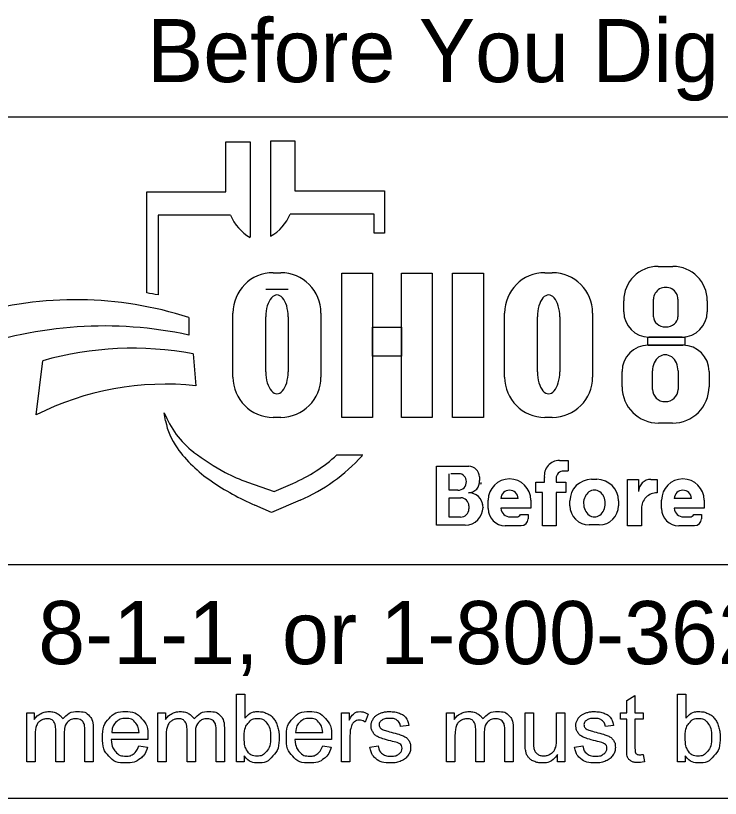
# Model space of a CAD drawing. Extents: x 0 to 34, y 0 to 22.
# Drawn here: x 3.267 to 4.831, y 2.143 to 3.88 of the extents above; entities that cross this region are included whole.
import ezdxf

# ---------------------------------------------------------------- set-up
doc = ezdxf.new("R2010")
doc.units = 0
doc.layers.add('GM_X_Minor_Lake', color=7, linetype='Continuous')
doc.layers.add('GM_X_Minor_Lake_Text', color=7, linetype='Continuous')

msp = doc.modelspace()

# ---------------------------------------------------------------- linework, layer by layer
at = {"layer": 'GM_X_Minor_Lake'}
for p, q in [((3.7335, 3.4883), (3.7335, 3.5998)), ((3.7335, 3.5998), (3.7872, 3.5998)), ((3.7872, 3.5998), (3.7872, 3.3877)), ((3.8329, 3.39), (3.8329, 3.6021)), ((3.8329, 3.6021), (3.8865, 3.6021)), ((3.8865, 3.6021), (3.8865, 3.4906)), ((3.5576, 3.2644), (3.5576, 3.4883)), ((3.5576, 3.4883), (3.7335, 3.4883)), ((3.8865, 3.4906), (4.0857, 3.4906)), ((4.0857, 3.4906), (4.0857, 3.3968)), ((4.0625, 3.4392), (3.8761, 3.4392)), ((4.0625, 3.3968), (4.0625, 3.4392)), ((3.5828, 3.4369), (3.5828, 3.26)), ((3.7439, 3.4369), (3.5828, 3.4369)), ((4.0857, 3.3968), (4.0625, 3.3968)), ((4.6931, 3.3231), (4.7258, 3.3231)), ((3.8385, 3.3091), (3.8551, 3.3091)), ((4.4416, 3.3091), (4.4581, 3.3091)), ((3.8718, 3.2721), (3.822, 3.2721)), ((4.683, 3.2111), (4.683, 3.2504)), ((4.7371, 3.2504), (4.7371, 3.2111)), ((4.6168, 3.2225), (4.6168, 3.2468)), ((4.8022, 3.2468), (4.8022, 3.2225)), ((3.7491, 3.0776), (3.7491, 3.2196)), ((3.9445, 3.2196), (3.9445, 3.0776)), ((4.3521, 3.0776), (4.3521, 3.2196)), ((4.5476, 3.2196), (4.5476, 3.0776)), ((3.6509, 3.2097), (3.6509, 3.1709)), ((3.822, 3.089), (3.822, 3.2114)), ((3.8718, 3.2114), (3.8718, 3.089)), ((4.425, 3.089), (4.425, 3.2114)), ((4.4748, 3.2114), (4.4748, 3.089)), ((4.7462, 3.1665), (4.6728, 3.1665)), ((4.671, 3.1482), (4.7483, 3.1482)), ((3.6608, 3.1291), (3.6671, 3.0582)), ((3.312, 2.9936), (3.3267, 3.1137)), ((4.6131, 3.0563), (4.6131, 3.0903)), ((4.6806, 3.0503), (4.6806, 3.0912)), ((4.7374, 3.0912), (4.7374, 3.0503)), ((4.8062, 3.0903), (4.8062, 3.0563)), ((3.5997, 2.9807), (3.5967, 2.9986)), ((3.8551, 2.9882), (3.8385, 2.9882)), ((4.4581, 2.9882), (4.4416, 2.9882)), ((4.7252, 2.9753), (4.6941, 2.9753)), ((3.98, 2.9048), (4.0375, 2.9048)), ((4.4739, 2.8926), (4.4934, 2.8926)), ((4.4934, 2.8926), (4.4934, 2.8696)), ((4.2013, 2.749), (4.2013, 2.8798)), ((4.2013, 2.8798), (4.2725, 2.8798)), ((4.4934, 2.8691), (4.4832, 2.8691)), ((4.2293, 2.8263), (4.2293, 2.8632)), ((4.2545, 2.8632), (4.2332, 2.8632)), ((4.2963, 2.856), (4.2963, 2.8481)), ((4.4406, 2.8442), (4.4406, 2.8546)), ((4.4667, 2.8526), (4.4667, 2.8442)), ((4.5451, 2.8508), (4.5573, 2.8508)), ((4.6254, 2.7478), (4.6254, 2.8505)), ((4.6254, 2.8505), (4.6499, 2.8505)), ((4.6499, 2.8505), (4.6499, 2.8237)), ((4.6772, 2.8505), (4.691, 2.8505)), ((4.691, 2.8505), (4.691, 2.8209)), ((3.7816, 2.8444), (3.841, 2.8239)), ((3.841, 2.8239), (3.8821, 2.8417)), ((4.4213, 2.8212), (4.4213, 2.8442)), ((4.4213, 2.8442), (4.4406, 2.8442)), ((4.4667, 2.8442), (4.4883, 2.8442)), ((4.4883, 2.8442), (4.4883, 2.8212)), ((4.2487, 2.8263), (4.2293, 2.8263)), ((4.4362, 2.8212), (4.4213, 2.8212)), ((4.4362, 2.7478), (4.4362, 2.8212)), ((4.4883, 2.8212), (4.4667, 2.8212)), ((4.4667, 2.8212), (4.4667, 2.7478)), ((3.8983, 2.8044), (3.835, 2.7769)), ((4.2293, 2.7669), (4.2293, 2.8097)), ((4.2293, 2.8097), (4.2548, 2.8097)), ((4.3159, 2.7858), (4.3159, 2.8042)), ((4.3824, 2.8082), (4.3439, 2.8082)), ((4.4104, 2.8042), (4.4104, 2.7866)), ((4.4973, 2.7922), (4.4973, 2.8029)), ((4.6051, 2.8029), (4.6051, 2.7922)), ((4.7008, 2.7858), (4.7008, 2.8042)), ((4.7674, 2.8082), (4.7288, 2.8082)), ((4.7953, 2.8042), (4.7953, 2.7866)), ((3.835, 2.7769), (3.7976, 2.7934)), ((4.2729, 2.7916), (4.2729, 2.7853)), ((4.3043, 2.7887), (4.3043, 2.7884)), ((4.4104, 2.7866), (4.344, 2.7866)), ((4.6559, 2.786), (4.6559, 2.7478)), ((4.7953, 2.7866), (4.7289, 2.7866)), ((4.2546, 2.7669), (4.2293, 2.7669)), ((4.3649, 2.7673), (4.379, 2.7673)), ((4.3876, 2.7729), (4.4045, 2.7729)), ((4.4045, 2.7729), (4.4045, 2.7631)), ((4.7498, 2.7673), (4.7639, 2.7673)), ((4.7725, 2.7729), (4.7894, 2.7729)), ((4.7894, 2.7729), (4.7894, 2.7631)), ((4.265, 2.749), (4.2013, 2.749)), ((4.3892, 2.7478), (4.3538, 2.7478)), ((4.4667, 2.7478), (4.4362, 2.7478)), ((4.5623, 2.7494), (4.5401, 2.7494)), ((4.6559, 2.7478), (4.6254, 2.7478)), ((4.7742, 2.7478), (4.7388, 2.7478))]:
    msp.add_line(p, q, dxfattribs=at)
for points in [[(3.991, 3.3081), (4.0589, 3.3081), (4.0589, 2.9881), (3.991, 2.9881)], [(4.1231, 3.3081), (4.1911, 3.3081), (4.1911, 2.9881), (4.1231, 2.9881)], [(4.2364, 3.3081), (4.3052, 3.3081), (4.3052, 2.9881), (4.2364, 2.9881)], [(4.0589, 3.1882), (4.1231, 3.1882), (4.1231, 3.1242), (4.0589, 3.1242)], [(4.6706, 3.1665), (4.7523, 3.1665), (4.7523, 3.1481), (4.6706, 3.1481)]]:
    msp.add_lwpolyline(points, close=True, dxfattribs=at)
for points in [[(3.7743, 2.2239), (3.7573, 2.2239), (3.7573, 2.3741), (3.7757, 2.3741), (3.7757, 2.3206)], [(4.6233, 2.2558), (4.6233, 2.3185), (4.6097, 2.3185), (4.6097, 2.3328), (4.6233, 2.3328), (4.6233, 2.3597), (4.6417, 2.3708), (4.6417, 2.3328), (4.6601, 2.3328), (4.6601, 2.3185), (4.6417, 2.3185), (4.6417, 2.2547)], [(4.7534, 2.2239), (4.7363, 2.2239), (4.7363, 2.3741), (4.7548, 2.3741), (4.7548, 2.3206)], [(3.2912, 2.2239), (3.2912, 2.3328), (3.3077, 2.3328), (3.3077, 2.3174)], [(3.5826, 2.2239), (3.5826, 2.3328), (3.5991, 2.3328), (3.5991, 2.3174)], [(3.9904, 2.2239), (3.9904, 2.3328), (4.007, 2.3328), (4.007, 2.3163)], [(4.0495, 2.3293), (4.043, 2.3122)], [(4.2236, 2.2239), (4.2236, 2.3328), (4.2401, 2.3328), (4.2401, 2.3174)], [(4.3979, 2.2654), (4.3979, 2.3328), (4.4164, 2.3328), (4.4164, 2.2724)], [(4.4676, 2.2745), (4.4676, 2.3328), (4.4861, 2.3328), (4.4861, 2.2239), (4.4696, 2.2239)], [(3.3743, 2.2871), (3.3743, 2.2239), (3.3559, 2.2239), (3.3559, 2.2946)], [(3.4388, 2.2986), (3.4388, 2.2239), (3.4203, 2.2239), (3.4203, 2.2924)], [(3.6657, 2.2871), (3.6657, 2.2239), (3.6473, 2.2239), (3.6473, 2.2946)], [(3.7301, 2.2986), (3.7301, 2.2239), (3.7117, 2.2239), (3.7117, 2.2924)], [(4.1394, 2.3046), (4.1213, 2.3022)], [(4.3067, 2.2871), (4.3067, 2.2239), (4.2883, 2.2239), (4.2883, 2.2946)], [(4.3711, 2.2986), (4.3711, 2.2239), (4.3527, 2.2239), (4.3527, 2.2924)], [(4.594, 2.3046), (4.5759, 2.3022)], [(3.3097, 2.2803), (3.3097, 2.2239), (3.2912, 2.2239)], [(3.4799, 2.2887), (3.5406, 2.2887)], [(3.601, 2.2803), (3.601, 2.2239), (3.5826, 2.2239)], [(3.8879, 2.2887), (3.9486, 2.2887)], [(4.0088, 2.2809), (4.0088, 2.2239), (3.9904, 2.2239)], [(4.242, 2.2803), (4.242, 2.2239), (4.2236, 2.2239)], [(3.56, 2.2736), (3.4788, 2.2736)], [(3.5404, 2.2591), (3.5595, 2.2567)], [(3.968, 2.2736), (3.8868, 2.2736)], [(3.9484, 2.2591), (3.9675, 2.2567)], [(4.053, 2.2564), (4.0712, 2.2593)], [(4.5076, 2.2564), (4.5258, 2.2593)], [(3.7743, 2.2375), (3.7743, 2.2239)], [(4.4696, 2.2239), (4.4696, 2.24)], [(4.6601, 2.2404), (4.6628, 2.2241)], [(4.7534, 2.2375), (4.7534, 2.2239)]]:
    msp.add_lwpolyline(points, dxfattribs=at)
for centre, radius, start, end in [((3.7847, 3.476), 0.0985, 299.2531, 338.0704), ((3.8353, 3.4736), 0.0985, 201.9296, 240.7469), ((4.6931, 3.2468), 0.0763, 90, 180), ((4.7258, 3.2468), 0.0763, 0, 90), ((3.8385, 3.2196), 0.0895, 90, 180), ((3.8551, 3.2196), 0.0895, 0, 90), ((4.4416, 3.2196), 0.0895, 90, 180), ((4.4581, 3.2196), 0.0895, 0, 90), ((3.3997, 2.4302), 0.8191, 72.1402, 106.3144), ((3.4295, 2.4554), 0.8191, 79.2074, 81.0007), ((4.6728, 3.2225), 0.056, 180, 270), ((4.7462, 3.2225), 0.056, 270, 0), ((3.4628, 2.2991), 0.8919, 77.8238, 109.8274), ((4.671, 3.0903), 0.0579, 90, 180), ((4.7483, 3.0903), 0.0579, 0, 90), ((3.5267, 2.4094), 0.7322, 79.44, 105.8467), ((3.8385, 3.0776), 0.0895, 180, 270), ((3.8551, 3.0776), 0.0895, 270, 0), ((4.4416, 3.0776), 0.0895, 180, 270), ((4.4581, 3.0776), 0.0895, 270, 0), ((3.5987, 2.4262), 0.6357, 83.8248, 116.8021), ((4.6941, 3.0563), 0.081, 180, 270), ((4.7252, 3.0563), 0.081, 270, 0), ((3.7841, 3.0707), 0.2008, 201.0457, 232.5314), ((3.741, 3.0048), 0.1433, 189.6817, 216.0884), ((3.8747, 3.1022), 0.3088, 216.0884, 235.7167), ((3.9766, 3.3219), 0.5173, 232.5314, 241.794), ((3.7387, 3.1722), 0.3602, 293.4582, 312.0712), ((3.7387, 3.1722), 0.401, 293.4582, 317.8286), ((4.4739, 2.859), 0.0335, 90, 187.5187), ((3.8914, 3.1631), 0.3371, 241.794, 250.9821), ((4.2725, 2.856), 0.0238, 0, 90), ((4.4832, 2.8526), 0.0165, 90, 180), ((4.2505, 2.8463), 0.0169, 357.8325, 90), ((4.3631, 2.8042), 0.0473, 0, 180), ((4.5451, 2.8029), 0.0478, 90, 180), ((4.5573, 2.8029), 0.0478, 0, 90), ((4.6768, 2.8237), 0.0269, 89.2449, 180), ((4.7481, 2.8042), 0.0473, 0, 180), ((4.0412, 3.3465), 0.6044, 235.7167, 246.2325), ((4.2487, 2.845), 0.0187, 270, 2.0582), ((4.2721, 2.8453), 0.0243, 270, 6.6529), ((4.2827, 2.8438), 0.0175, 347.4023, 0), ((4.2722, 2.7889), 0.0321, 4.0748, 90), ((4.3632, 2.8072), 0.0193, 2.9632, 177.0368), ((4.6908, 2.786), 0.0349, 89.6033, 180), ((4.7481, 2.8072), 0.0193, 2.9632, 177.0368), ((4.2548, 2.7916), 0.0181, 0, 90), ((4.2546, 2.7853), 0.0184, 270, 0), ((4.265, 2.7884), 0.0393, 270, 0), ((4.2714, 2.7887), 0.033, 0, 11.7502), ((4.3538, 2.7858), 0.038, 180, 270), ((4.3649, 2.7883), 0.021, 184.827, 270), ((4.5401, 2.7922), 0.0428, 180, 270), ((4.5623, 2.7922), 0.0428, 270, 0), ((4.7388, 2.7858), 0.038, 180, 270), ((4.7498, 2.7883), 0.021, 184.827, 270), ((4.379, 2.7767), 0.00938, 270, 335.9979), ((4.3892, 2.7631), 0.0152, 270, 0), ((4.7639, 2.7767), 0.00938, 270, 335.9979), ((4.7742, 2.7631), 0.0152, 270, 0)]:
    msp.add_arc(centre, radius, start, end, dxfattribs=at)
for centre, major_axis, ratio, start_param, end_param in [((4.71, 3.2504), (0.0271, 0), 0.969373, 0, 3.141593), ((3.8469, 3.2114), (0, 0.0484), 0.514403, 4.712389, 7.853982), ((4.4499, 3.2114), (0, 0.0484), 0.514403, 4.712389, 7.853982), ((4.71, 3.2111), (0.0271, 0), 0.818453, 3.141593, 6.283185), ((4.709, 3.0912), (0, 0.0358), 0.794529, 4.712389, 7.853982), ((3.8469, 3.089), (0, 0.0484), 0.514403, 1.570796, 4.712389), ((4.4499, 3.089), (0, 0.0484), 0.514403, 1.570796, 4.712389), ((4.709, 3.0503), (0.0284, 0), 0.959837, 3.141593, 6.283185), ((4.5517, 2.7976), (0, 0.029), 0.832186, 4.712389, 7.853982), ((4.5517, 2.7976), (0, 0.0302), 0.797287, 1.570796, 4.712389)]:
    msp.add_ellipse(centre, major_axis=major_axis, ratio=ratio, start_param=start_param, end_param=end_param, dxfattribs=at)
for points in [[(3.3077, 2.3174), (3.3128, 2.3254), (3.3214, 2.3303), (3.3299, 2.3352), (3.3407, 2.3352), (3.3528, 2.3352), (3.3606, 2.3301), (3.3683, 2.3251), (3.3715, 2.3161), (3.3844, 2.3352), (3.4051, 2.3352), (3.4213, 2.3352), (3.43, 2.3262), (3.4388, 2.3172), (3.4388, 2.2986)], [(3.5595, 2.2567), (3.555, 2.24), (3.5428, 2.2307), (3.5306, 2.2215), (3.5117, 2.2215), (3.4878, 2.2215), (3.4738, 2.2362), (3.4598, 2.2509), (3.4598, 2.2774), (3.4598, 2.3049), (3.474, 2.32), (3.4881, 2.3352), (3.5106, 2.3352), (3.5324, 2.3352), (3.5463, 2.3203), (3.5601, 2.3055), (3.5601, 2.2785), (3.5601, 2.2769), (3.56, 2.2736)], [(3.5991, 2.3174), (3.6042, 2.3254), (3.6127, 2.3303), (3.6212, 2.3352), (3.6321, 2.3352), (3.6442, 2.3352), (3.6519, 2.3301), (3.6597, 2.3251), (3.6628, 2.3161), (3.6758, 2.3352), (3.6965, 2.3352), (3.7127, 2.3352), (3.7214, 2.3262), (3.7301, 2.3172), (3.7301, 2.2986)], [(3.7757, 2.3206), (3.7874, 2.3352), (3.8055, 2.3352), (3.8155, 2.3352), (3.8245, 2.3311), (3.8335, 2.3271), (3.8392, 2.3198), (3.845, 2.3124), (3.8483, 2.3021), (3.8516, 2.2918), (3.8516, 2.28), (3.8516, 2.252), (3.8378, 2.2368), (3.8239, 2.2215), (3.8046, 2.2215), (3.7853, 2.2215), (3.7743, 2.2375)], [(3.9675, 2.2567), (3.963, 2.24), (3.9508, 2.2307), (3.9386, 2.2215), (3.9196, 2.2215), (3.8958, 2.2215), (3.8818, 2.2362), (3.8678, 2.2509), (3.8678, 2.2774), (3.8678, 2.3049), (3.882, 2.32), (3.8961, 2.3352), (3.9186, 2.3352), (3.9404, 2.3352), (3.9543, 2.3203), (3.9681, 2.3055), (3.9681, 2.2785), (3.9681, 2.2769), (3.968, 2.2736)], [(4.007, 2.3163), (4.0133, 2.3278), (4.0187, 2.3315), (4.0241, 2.3352), (4.0305, 2.3352), (4.0398, 2.3352), (4.0495, 2.3293)], [(4.0712, 2.2593), (4.0727, 2.2483), (4.0798, 2.2425), (4.0868, 2.2366), (4.0995, 2.2366), (4.1122, 2.2366), (4.1184, 2.2418), (4.1245, 2.247), (4.1245, 2.254), (4.1245, 2.2602), (4.1191, 2.2638), (4.1153, 2.2663), (4.1002, 2.2701), (4.0799, 2.2752), (4.072, 2.2789), (4.0642, 2.2827), (4.0601, 2.2893), (4.0561, 2.2959), (4.0561, 2.3038), (4.0561, 2.3111), (4.0594, 2.3173), (4.0628, 2.3235), (4.0685, 2.3276), (4.0728, 2.3308), (4.0803, 2.333), (4.0877, 2.3352), (4.0962, 2.3352), (4.109, 2.3352), (4.1187, 2.3315), (4.1284, 2.3278), (4.133, 2.3215), (4.1377, 2.3152), (4.1394, 2.3046)], [(4.2401, 2.3174), (4.2452, 2.3254), (4.2537, 2.3303), (4.2622, 2.3352), (4.2731, 2.3352), (4.2852, 2.3352), (4.2929, 2.3301), (4.3007, 2.3251), (4.3038, 2.3161), (4.3168, 2.3352), (4.3375, 2.3352), (4.3537, 2.3352), (4.3624, 2.3262), (4.3711, 2.3172), (4.3711, 2.2986)], [(4.5258, 2.2593), (4.5273, 2.2483), (4.5343, 2.2425), (4.5414, 2.2366), (4.554, 2.2366), (4.5668, 2.2366), (4.5729, 2.2418), (4.5791, 2.247), (4.5791, 2.254), (4.5791, 2.2602), (4.5736, 2.2638), (4.5698, 2.2663), (4.5548, 2.2701), (4.5345, 2.2752), (4.5266, 2.2789), (4.5188, 2.2827), (4.5147, 2.2893), (4.5107, 2.2959), (4.5107, 2.3038), (4.5107, 2.3111), (4.514, 2.3173), (4.5173, 2.3235), (4.5231, 2.3276), (4.5274, 2.3308), (4.5348, 2.333), (4.5423, 2.3352), (4.5508, 2.3352), (4.5636, 2.3352), (4.5733, 2.3315), (4.583, 2.3278), (4.5876, 2.3215), (4.5922, 2.3152), (4.594, 2.3046)], [(4.7548, 2.3206), (4.7664, 2.3352), (4.7846, 2.3352), (4.7946, 2.3352), (4.8036, 2.3311), (4.8125, 2.3271), (4.8183, 2.3198), (4.8241, 2.3124), (4.8274, 2.3021), (4.8306, 2.2918), (4.8306, 2.28), (4.8306, 2.252), (4.8168, 2.2368), (4.803, 2.2215), (4.7836, 2.2215), (4.7644, 2.2215), (4.7534, 2.2375)], [(3.3559, 2.2946), (3.3559, 2.3069), (3.3514, 2.313), (3.3469, 2.3191), (3.3366, 2.3191), (3.3288, 2.3191), (3.3222, 2.315), (3.3156, 2.311), (3.3126, 2.3031), (3.3097, 2.2952), (3.3097, 2.2803)], [(3.4203, 2.2924), (3.4203, 2.3035), (3.4185, 2.3083), (3.4168, 2.3132), (3.412, 2.3162), (3.4073, 2.3191), (3.401, 2.3191), (3.3895, 2.3191), (3.3819, 2.3115), (3.3743, 2.3039), (3.3743, 2.2871)], [(3.5406, 2.2887), (3.5394, 2.3025), (3.5337, 2.3094), (3.5249, 2.3201), (3.5108, 2.3201), (3.4981, 2.3201), (3.4894, 2.3115), (3.4808, 2.303), (3.4799, 2.2887)], [(3.6473, 2.2946), (3.6473, 2.3069), (3.6428, 2.313), (3.6383, 2.3191), (3.628, 2.3191), (3.6202, 2.3191), (3.6136, 2.315), (3.607, 2.311), (3.604, 2.3031), (3.601, 2.2952), (3.601, 2.2803)], [(3.7117, 2.2924), (3.7117, 2.3035), (3.7099, 2.3083), (3.7081, 2.3132), (3.7034, 2.3162), (3.6987, 2.3191), (3.6923, 2.3191), (3.6809, 2.3191), (3.6733, 2.3115), (3.6657, 2.3039), (3.6657, 2.2871)], [(3.7741, 2.2792), (3.7741, 2.2596), (3.7794, 2.2509), (3.7881, 2.2366), (3.8029, 2.2366), (3.815, 2.2366), (3.8238, 2.2471), (3.8326, 2.2576), (3.8326, 2.2784), (3.8326, 2.2998), (3.8241, 2.3099), (3.8157, 2.3201), (3.8038, 2.3201), (3.7917, 2.3201), (3.7829, 2.3096), (3.7741, 2.299), (3.7741, 2.2792)], [(3.9486, 2.2887), (3.9474, 2.3025), (3.9417, 2.3094), (3.9328, 2.3201), (3.9188, 2.3201), (3.9061, 2.3201), (3.8974, 2.3115), (3.8888, 2.303), (3.8879, 2.2887)], [(4.043, 2.3122), (4.0363, 2.3162), (4.0295, 2.3162), (4.0235, 2.3162), (4.0187, 2.3125), (4.0139, 2.3089), (4.0119, 2.3024), (4.0088, 2.2926), (4.0088, 2.2809)], [(4.1213, 2.3022), (4.1201, 2.3106), (4.1142, 2.3153), (4.1083, 2.3201), (4.0975, 2.3201), (4.0848, 2.3201), (4.0794, 2.3159), (4.0739, 2.3116), (4.0739, 2.306), (4.0739, 2.3024), (4.0762, 2.2995), (4.0785, 2.2966), (4.0833, 2.2946), (4.086, 2.2936), (4.0996, 2.2899), (4.1192, 2.2847), (4.1269, 2.2813), (4.1347, 2.278), (4.1391, 2.2717), (4.1435, 2.2653), (4.1435, 2.2559), (4.1435, 2.2467), (4.1381, 2.2386), (4.1327, 2.2304), (4.1226, 2.226), (4.1124, 2.2215), (4.0996, 2.2215), (4.0784, 2.2215), (4.0672, 2.2303), (4.0561, 2.2391), (4.053, 2.2564)], [(4.2883, 2.2946), (4.2883, 2.3069), (4.2838, 2.313), (4.2793, 2.3191), (4.269, 2.3191), (4.2612, 2.3191), (4.2546, 2.315), (4.248, 2.311), (4.245, 2.3031), (4.242, 2.2952), (4.242, 2.2803)], [(4.3527, 2.2924), (4.3527, 2.3035), (4.3509, 2.3083), (4.3491, 2.3132), (4.3444, 2.3162), (4.3397, 2.3191), (4.3333, 2.3191), (4.3219, 2.3191), (4.3143, 2.3115), (4.3067, 2.3039), (4.3067, 2.2871)], [(4.5759, 2.3022), (4.5747, 2.3106), (4.5688, 2.3153), (4.5629, 2.3201), (4.5521, 2.3201), (4.5394, 2.3201), (4.5339, 2.3159), (4.5285, 2.3116), (4.5285, 2.306), (4.5285, 2.3024), (4.5308, 2.2995), (4.533, 2.2966), (4.5378, 2.2946), (4.5406, 2.2936), (4.5542, 2.2899), (4.5737, 2.2847), (4.5815, 2.2813), (4.5893, 2.278), (4.5937, 2.2717), (4.5981, 2.2653), (4.5981, 2.2559), (4.5981, 2.2467), (4.5927, 2.2386), (4.5873, 2.2304), (4.5772, 2.226), (4.567, 2.2215), (4.5542, 2.2215), (4.5329, 2.2215), (4.5218, 2.2303), (4.5107, 2.2391), (4.5076, 2.2564)], [(4.7532, 2.2792), (4.7532, 2.2596), (4.7585, 2.2509), (4.7672, 2.2366), (4.782, 2.2366), (4.7941, 2.2366), (4.8029, 2.2471), (4.8116, 2.2576), (4.8116, 2.2784), (4.8116, 2.2998), (4.8032, 2.3099), (4.7948, 2.3201), (4.7828, 2.3201), (4.7708, 2.3201), (4.762, 2.3096), (4.7532, 2.299), (4.7532, 2.2792)], [(3.4788, 2.2736), (3.4799, 2.2557), (3.489, 2.2462), (3.4981, 2.2366), (3.5117, 2.2366), (3.5219, 2.2366), (3.5291, 2.242), (3.5362, 2.2473), (3.5404, 2.2591)], [(3.8868, 2.2736), (3.8879, 2.2557), (3.897, 2.2462), (3.9061, 2.2366), (3.9197, 2.2366), (3.9299, 2.2366), (3.937, 2.242), (3.9442, 2.2473), (3.9484, 2.2591)], [(4.4696, 2.24), (4.4569, 2.2215), (4.4351, 2.2215), (4.4255, 2.2215), (4.4171, 2.2252), (4.4088, 2.2289), (4.4047, 2.2345), (4.4007, 2.2401), (4.3991, 2.2482), (4.3979, 2.2536), (4.3979, 2.2654)], [(4.4164, 2.2724), (4.4164, 2.258), (4.4175, 2.253), (4.4192, 2.2457), (4.4249, 2.2416), (4.4305, 2.2374), (4.4388, 2.2374), (4.4471, 2.2374), (4.4543, 2.2417), (4.4616, 2.2459), (4.4646, 2.2533), (4.4676, 2.2606), (4.4676, 2.2745)], [(4.6628, 2.2241), (4.655, 2.2224), (4.6488, 2.2224), (4.6388, 2.2224), (4.6333, 2.2256), (4.6278, 2.2288), (4.6255, 2.234), (4.6233, 2.2392), (4.6233, 2.2558)], [(4.6417, 2.2547), (4.6417, 2.2468), (4.6427, 2.2445), (4.6436, 2.2423), (4.6458, 2.2409), (4.648, 2.2396), (4.6521, 2.2396), (4.6551, 2.2396), (4.6601, 2.2404)]]:
    msp.add_open_spline(points, degree=3, dxfattribs=at)
at = {"layer": 'GM_X_Minor_Lake_Text'}
for p, q in [((2.3775, 3.6553), (6.6275, 3.6553)), ((6.6275, 2.6607), (2.3775, 2.6607)), ((6.6275, 2.1428), (2.3775, 2.1428))]:
    msp.add_line(p, q, dxfattribs=at)

# ---------------------------------------------------------------- texts
at = {"layer": 'GM_X_Minor_Lake'}
for s, p in [('Before You Dig', (3.5583, 3.7321)), ('OHIO811, 8-1-1, or 1-800-362-2764', (2.422, 2.4406))]:
    msp.add_text(s, height=0.14, dxfattribs=at).set_placement(p)

doc.saveas('drawing.dxf')
